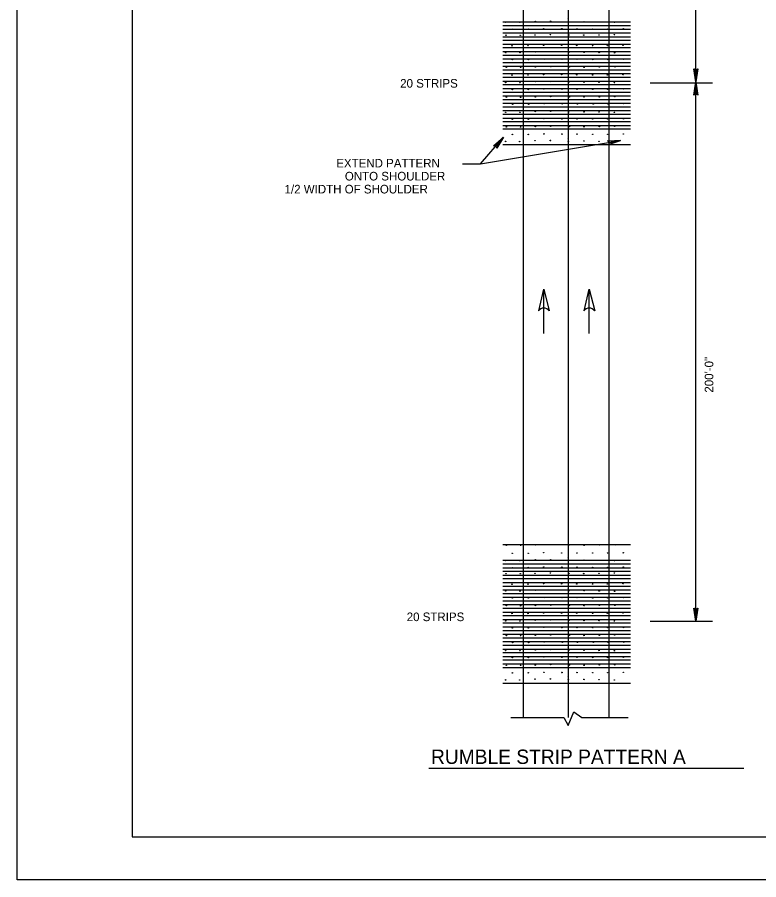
# Model space of a CAD drawing. Extents: x 632008 to 634206, y 294231 to 297795.
# Drawn here: x 632007.9 to 632266.3, y 294230.6 to 294531.2 of the extents above; entities that cross this region are included whole.
import ezdxf

# ---------------------------------------------------------------- set-up
doc = ezdxf.new("R2010")
doc.units = 0
for name, color, linetype in [('1', 7, 'Continuous'), ('Level 2', 7, 'Continuous'), ('Level 3', 7, 'Continuous'), ('PLT-BNDY', 7, 'Continuous')]:
    doc.layers.add(name, color=color, linetype=linetype)

msp = doc.modelspace()

# ---------------------------------------------------------------- linework, layer by layer
at = {"layer": '1'}
msp.add_line((632151.27, 294269.52), (632261.11, 294269.52), dxfattribs=at)
msp.add_lwpolyline([(632833.86, 294245.62), (632833.86, 294809.62), (632047.86, 294809.62), (632047.86, 294245.62), (632833.86, 294245.62), (632833.86, 294271.98), (632633.86, 294271.98), (632633.86, 294336.66), (632833.86, 294336.66), (632833.86, 294365.62), (632633.86, 294365.62), (632633.86, 294245.62), (632712.66, 294245.62), (632712.66, 294271.98), (632712.66, 294245.62), (632789.66, 294245.62), (632789.66, 294271.98), (632789.66, 294259.66), (632833.86, 294259.66)], dxfattribs=at)
at = {"layer": 'Level 2'}
for p, q in [((632184.14, 294798.62), (632184.14, 294287.21)), ((632199.8, 294798.62), (632199.8, 294287.21)), ((632214.15, 294287.21), (632214.15, 294798.62)), ((632244.33, 294508.63), (632244.33, 294602.6)), ((632177.04, 294529.55), (632221.52, 294529.55)), ((632199.63, 294530.56), (632199.63, 294530.56)), ((632177.04, 294528.31), (632221.52, 294528.31)), ((632177.04, 294526.97), (632221.52, 294526.97)), ((632177.04, 294525.73), (632221.52, 294525.73)), ((632177.04, 294524.4), (632221.52, 294524.4)), ((632177.04, 294523.16), (632221.52, 294523.16)), ((632177.04, 294521.82), (632221.52, 294521.82)), ((632177.04, 294520.58), (632221.52, 294520.58)), ((632199.63, 294519.84), (632199.63, 294519.84)), ((632177.04, 294519.24), (632221.52, 294519.24)), ((632177.04, 294518), (632221.52, 294518)), ((632177.04, 294516.67), (632221.52, 294516.67)), ((632177.04, 294515.42), (632221.52, 294515.42)), ((632177.04, 294514.09), (632221.52, 294514.09)), ((632177.04, 294512.85), (632221.52, 294512.85)), ((632177.04, 294511.51), (632221.52, 294511.51)), ((632177.04, 294510.27), (632221.52, 294510.27)), ((632177.04, 294508.94), (632221.52, 294508.94)), ((632177.04, 294507.69), (632221.52, 294507.69)), ((632199.63, 294509.5), (632199.63, 294509.5)), ((632228.37, 294508.32), (632250.14, 294508.32)), ((632244.33, 294320.68), (632244.33, 294508.63)), ((632177.04, 294506.36), (632221.52, 294506.36)), ((632177.04, 294505.12), (632221.52, 294505.12)), ((632177.04, 294503.78), (632221.52, 294503.78)), ((632177.04, 294502.54), (632221.52, 294502.54)), ((632177.04, 294501.2), (632221.52, 294501.2)), ((632177.04, 294499.96), (632221.52, 294499.96)), ((632177.04, 294498.63), (632221.52, 294498.63)), ((632199.63, 294499.13), (632199.63, 294499.13)), ((632177.04, 294497.39), (632221.52, 294497.39)), ((632177.04, 294496.05), (632221.52, 294496.05)), ((632177.04, 294494.81), (632221.52, 294494.81)), ((632177.04, 294493.47), (632221.52, 294493.47)), ((632169.32, 294480.08), (632177.28, 294489.35)), ((632177.04, 294492.23), (632221.52, 294492.23)), ((632169.32, 294480.08), (632218.08, 294488.19)), ((632177.04, 294486.77), (632221.52, 294486.77)), ((632199.47, 294488.94), (632199.47, 294488.94)), ((632163, 294480.08), (632169.32, 294480.08)), ((632189.57, 294428.89), (632191.32, 294436.45)), ((632191.32, 294436.45), (632193.24, 294428.89)), ((632191.32, 294421), (632191.32, 294436.45)), ((632205.43, 294428.89), (632207.18, 294436.45)), ((632207.18, 294436.45), (632209.1, 294428.89)), ((632207.18, 294421), (632207.18, 294436.45)), ((632177.04, 294347.4), (632221.52, 294347.4)), ((632199.63, 294342.96), (632199.63, 294342.96)), ((632177.04, 294341.94), (632221.52, 294341.94)), ((632177.04, 294340.7), (632221.52, 294340.7)), ((632177.04, 294339.36), (632221.52, 294339.36)), ((632177.04, 294338.12), (632221.52, 294338.12)), ((632177.04, 294336.79), (632221.52, 294336.79)), ((632177.04, 294335.55), (632221.52, 294335.55)), ((632177.04, 294334.21), (632221.52, 294334.21)), ((632177.04, 294332.97), (632221.52, 294332.97)), ((632177.04, 294331.63), (632221.52, 294331.63)), ((632177.04, 294330.39), (632221.52, 294330.39)), ((632199.63, 294332.23), (632199.63, 294332.23)), ((632177.04, 294329.06), (632221.52, 294329.06)), ((632177.04, 294327.82), (632221.52, 294327.82)), ((632177.04, 294326.48), (632221.52, 294326.48)), ((632177.04, 294325.24), (632221.52, 294325.24)), ((632177.04, 294323.9), (632221.52, 294323.9)), ((632177.04, 294322.66), (632221.52, 294322.66)), ((632177.04, 294321.33), (632221.52, 294321.33)), ((632199.63, 294321.89), (632199.63, 294321.89)), ((632177.04, 294320.09), (632221.52, 294320.09)), ((632177.04, 294318.75), (632221.52, 294318.75)), ((632228.37, 294320.71), (632250.14, 294320.71)), ((632177.04, 294317.51), (632221.52, 294317.51)), ((632177.04, 294316.17), (632221.52, 294316.17)), ((632177.04, 294314.93), (632221.52, 294314.93)), ((632177.04, 294313.6), (632221.52, 294313.6)), ((632177.04, 294312.36), (632221.52, 294312.36)), ((632177.04, 294311.02), (632221.52, 294311.02)), ((632177.04, 294309.78), (632221.52, 294309.78)), ((632199.63, 294311.52), (632199.63, 294311.52)), ((632177.04, 294308.44), (632221.52, 294308.44)), ((632177.04, 294307.2), (632221.52, 294307.2)), ((632177.04, 294305.87), (632221.52, 294305.87)), ((632177.04, 294304.63), (632221.52, 294304.63)), ((632199.47, 294301.33), (632199.47, 294301.33)), ((632177.04, 294299.16), (632221.52, 294299.16))]:
    msp.add_line(p, q, dxfattribs=at)
for centre in [(632178.08, 294529.45), (632183, 294529.42), (632188.38, 294529.73), (632193.73, 294529.8), (632199.99, 294529.52), (632199.99, 294529.52), (632205.37, 294529.59), (632210.62, 294529.52), (632215.97, 294529.41), (632180.38, 294527.01), (632185.94, 294527.02), (632191.35, 294527.21), (632197.64, 294527.14), (632202.92, 294527.12), (632208.41, 294527.08), (632213.59, 294527.08), (632219.07, 294527.17), (632178.21, 294524.91), (632183.13, 294524.88), (632188.29, 294524.98), (632193.67, 294525.1), (632200.12, 294524.98), (632205.3, 294524.94), (632210.59, 294525.01), (632215.99, 294525.09), (632180.3, 294521.22), (632185.86, 294521.24), (632191.27, 294521.42), (632197.57, 294521.35), (632202.85, 294521.34), (632208.34, 294521.29), (632213.51, 294521.29), (632218.99, 294521.39), (632178.11, 294518.83), (632180.41, 294516.38), (632183.03, 294518.8), (632185.97, 294516.4), (632188.41, 294519.1), (632191.38, 294516.58), (632193.76, 294519.17), (632197.67, 294516.51), (632200.02, 294518.9), (632202.95, 294516.5), (632205.4, 294518.97), (632208.44, 294516.45), (632210.65, 294518.9), (632213.62, 294516.45), (632216, 294518.78), (632219.1, 294516.55), (632178.33, 294513.72), (632183.26, 294513.7), (632188.42, 294513.8), (632193.79, 294513.92), (632200.24, 294513.8), (632205.42, 294513.76), (632210.71, 294513.83), (632216.12, 294513.91), (632180.3, 294511.01), (632185.86, 294511.02), (632191.27, 294511.21), (632197.57, 294511.14), (632202.85, 294511.12), (632208.34, 294511.08), (632213.51, 294511.08), (632218.99, 294511.17), (632178.09, 294508.43), (632183.02, 294508.4), (632188.4, 294508.71), (632193.75, 294508.78), (632200.01, 294508.5), (632205.39, 294508.57), (632210.63, 294508.5), (632215.99, 294508.38), (632180.39, 294505.98), (632185.95, 294506), (632191.37, 294506.19), (632197.66, 294506.12), (632202.94, 294506.1), (632208.43, 294506.06), (632213.6, 294506.06), (632219.08, 294506.15), (632178.32, 294503.33), (632183.24, 294503.3), (632188.4, 294503.4), (632193.78, 294503.52), (632200.23, 294503.4), (632205.4, 294503.36), (632210.7, 294503.43), (632216.1, 294503.51), (632180.53, 294500.87), (632186.09, 294500.88), (632188.4, 294498.34), (632191.5, 294501.07), (632193.75, 294498.41), (632197.79, 294501), (632203.08, 294500.99), (632203.08, 294500.99), (632205.39, 294498.2), (632208.57, 294500.94), (632213.74, 294500.94), (632219.22, 294501.03), (632178.09, 294498.06), (632180.39, 294495.61), (632183.02, 294498.03), (632185.95, 294495.63), (632191.37, 294495.82), (632197.66, 294495.75), (632200.01, 294498.13), (632202.94, 294495.73), (632208.43, 294495.69), (632210.63, 294498.13), (632213.6, 294495.69), (632213.6, 294495.69), (632215.99, 294498.01), (632219.08, 294495.78), (632178.32, 294492.96), (632183.24, 294492.93), (632188.4, 294493.03), (632193.78, 294493.15), (632200.23, 294493.03), (632205.4, 294492.99), (632210.7, 294493.06), (632216.1, 294493.14), (632180.39, 294490.32), (632185.95, 294490.33), (632191.37, 294490.52), (632197.66, 294490.45), (632202.94, 294490.44), (632208.43, 294490.39), (632213.6, 294490.39), (632219.08, 294490.48), (632178.02, 294487.88), (632182.94, 294487.85), (632188.32, 294488.15), (632193.67, 294488.22), (632199.93, 294487.95), (632205.31, 294488.02), (632210.56, 294487.95), (632215.91, 294487.83), (632178.33, 294347.17), (632183.26, 294347.14), (632188.42, 294347.24), (632200.24, 294347.24), (632205.42, 294347.2), (632210.71, 294347.27), (632216.12, 294347.35), (632180.35, 294344.38), (632185.91, 294344.39), (632188.38, 294342.12), (632191.32, 294344.58), (632193.73, 294342.19), (632197.61, 294344.51), (632199.99, 294341.92), (632199.99, 294341.92), (632202.89, 294344.49), (632205.37, 294341.99), (632208.38, 294344.45), (632210.62, 294341.92), (632213.56, 294344.45), (632219.04, 294344.54), (632178.08, 294341.84), (632180.38, 294339.4), (632183, 294341.81), (632185.94, 294339.41), (632191.35, 294339.6), (632197.64, 294339.53), (632202.92, 294339.52), (632208.41, 294339.47), (632213.59, 294339.47), (632215.97, 294341.8), (632219.07, 294339.56), (632178.21, 294337.3), (632183.13, 294337.27), (632188.29, 294337.37), (632193.67, 294337.49), (632200.12, 294337.37), (632205.3, 294337.33), (632210.59, 294337.4), (632215.99, 294337.48), (632180.3, 294333.61), (632185.86, 294333.63), (632191.27, 294333.82), (632197.57, 294333.75), (632202.85, 294333.73), (632208.34, 294333.69), (632213.51, 294333.69), (632218.99, 294333.78), (632178.11, 294331.22), (632183.03, 294331.19), (632188.41, 294331.5), (632193.76, 294331.57), (632200.02, 294331.29), (632205.4, 294331.36), (632210.65, 294331.29), (632216, 294331.17), (632180.41, 294328.77), (632185.97, 294328.79), (632191.38, 294328.98), (632197.67, 294328.91), (632202.95, 294328.89), (632208.44, 294328.85), (632213.62, 294328.85), (632219.1, 294328.94), (632178.33, 294326.12), (632183.26, 294326.09), (632188.42, 294326.19), (632193.79, 294326.31), (632200.24, 294326.19), (632205.42, 294326.15), (632210.71, 294326.22), (632216.12, 294326.3), (632180.3, 294323.4), (632185.86, 294323.41), (632188.4, 294321.1), (632191.27, 294323.6), (632193.75, 294321.17), (632197.57, 294323.53), (632200.01, 294320.89), (632202.85, 294323.52), (632205.39, 294320.96), (632208.34, 294323.47), (632210.63, 294320.89), (632213.51, 294323.47), (632218.99, 294323.56), (632178.09, 294320.82), (632180.39, 294318.38), (632183.02, 294320.79), (632185.95, 294318.39), (632191.37, 294318.58), (632197.66, 294318.51), (632202.94, 294318.49), (632208.43, 294318.45), (632213.6, 294318.45), (632215.99, 294320.78), (632219.08, 294318.54), (632178.32, 294315.72), (632183.24, 294315.69), (632188.4, 294315.79), (632193.78, 294315.91), (632200.23, 294315.79), (632205.4, 294315.75), (632210.7, 294315.82), (632216.1, 294315.9), (632180.53, 294313.26), (632186.09, 294313.28), (632191.5, 294313.46), (632197.79, 294313.39), (632203.08, 294313.38), (632203.08, 294313.38), (632208.57, 294313.33), (632213.74, 294313.33), (632219.22, 294313.43), (632178.09, 294310.45), (632183.02, 294310.42), (632188.4, 294310.73), (632193.75, 294310.8), (632200.01, 294310.53), (632205.39, 294310.6), (632210.63, 294310.53), (632215.99, 294310.41), (632180.39, 294308.01), (632185.95, 294308.02), (632191.37, 294308.21), (632197.66, 294308.14), (632202.94, 294308.12), (632208.43, 294308.08), (632213.6, 294308.08), (632213.6, 294308.08), (632219.08, 294308.17), (632178.32, 294305.35), (632183.24, 294305.32), (632188.4, 294305.42), (632191.37, 294302.92), (632193.78, 294305.54), (632200.23, 294305.42), (632205.4, 294305.38), (632210.7, 294305.45), (632216.1, 294305.53), (632219.08, 294302.88), (632178.02, 294300.27), (632180.39, 294302.71), (632182.94, 294300.24), (632185.95, 294302.73), (632188.32, 294300.54), (632193.67, 294300.61), (632197.66, 294302.84), (632199.93, 294300.34), (632202.94, 294302.83), (632205.31, 294300.41), (632208.43, 294302.79), (632210.56, 294300.34), (632213.6, 294302.79), (632215.91, 294300.22)]:
    msp.add_circle(centre, 0.0832, dxfattribs=at)
for centre in [(632191.33, 294427.47), (632207.19, 294427.47)]:
    msp.add_arc(centre, 2.34, 36.8699, 143.1301, dxfattribs=at)
at = {"layer": 'Level 3'}
for p, q in [((632199.87, 294284.41), (632201.79, 294289.13)), ((632201.79, 294289.13), (632204.6, 294287.21)), ((632179.85, 294287.21), (632198.28, 294287.21)), ((632198.28, 294287.21), (632199.87, 294284.41)), ((632204.6, 294287.21), (632220.75, 294287.21))]:
    msp.add_line(p, q, dxfattribs=at)
for points in [[(632244.87, 294513.03), (632244.52, 294512.84), (632244.33, 294508.63), (632244.87, 294513.03), (632245.04, 294513.19), (632244.33, 294508.63), (632244.17, 294512.84), (632243.82, 294513.03), (632244.33, 294508.63), (632243.63, 294513.19), (632243.82, 294513.03)], [(632243.82, 294504.25), (632244.17, 294504.41), (632244.33, 294508.63), (632243.82, 294504.25), (632243.63, 294504.06), (632244.33, 294508.63), (632244.52, 294504.41), (632244.87, 294504.25), (632244.33, 294508.63), (632245.04, 294504.06), (632244.87, 294504.25)], [(632174.13, 294486.45), (632174.49, 294486.33), (632177.28, 294489.35), (632174.13, 294486.45), (632173.78, 294486.4), (632177.28, 294489.35), (632174.7, 294486), (632174.94, 294485.68), (632177.28, 294489.35), (632174.96, 294485.5), (632174.94, 294485.68)], [(632213.8, 294487.95), (632214.01, 294487.63), (632218.08, 294488.19), (632213.8, 294487.95), (632213.5, 294488.14), (632218.08, 294488.19), (632213.97, 294487.24), (632213.94, 294486.85), (632218.08, 294488.19), (632213.84, 294486.69), (632213.94, 294486.85)], [(632244.87, 294325.09), (632244.52, 294324.9), (632244.33, 294320.68), (632244.87, 294325.09), (632245.04, 294325.25), (632244.33, 294320.68), (632244.17, 294324.9), (632243.82, 294325.09), (632244.33, 294320.68), (632243.63, 294325.25), (632243.82, 294325.09)]]:
    msp.add_lwpolyline(points, dxfattribs=at)
at = {"layer": 'PLT-BNDY'}
msp.add_lwpolyline([(632007.86, 294824.62), (632848.86, 294824.62), (632848.86, 294230.62), (632007.86, 294230.62)], close=True, dxfattribs=at)

# ---------------------------------------------------------------- texts
at = {"layer": 'Level 2'}
for s, height, p in [('20 STRIPS', 3, (632141.31, 294506.64)), ('EXTEND PATTERN', 3, (632119.02, 294478.82)), ('ONTO SHOULDER', 3, (632122.02, 294474.29)), ('1/2 WIDTH OF SHOULDER', 3, (632101.02, 294469.77)), ('20 STRIPS', 3, (632143.58, 294320.74)), ('RUMBLE STRIP PATTERN A', 5, (632152.05, 294270.98))]:
    msp.add_text(s, height=height, dxfattribs=at).set_placement(p)
msp.add_text('200\'-0"', height=3, rotation=90, dxfattribs=at).set_placement((632250.43, 294400.36))

doc.saveas('drawing.dxf')
